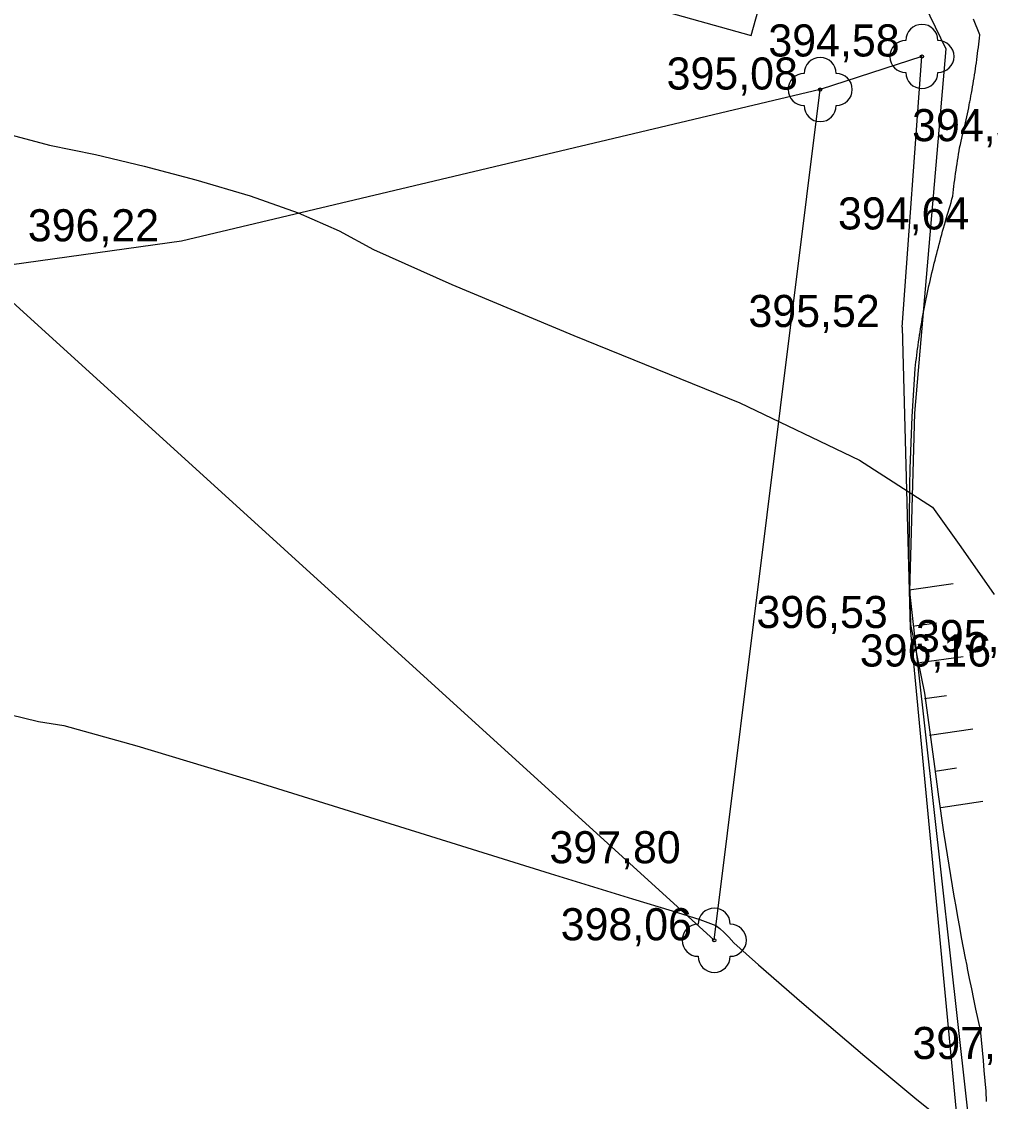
# Model space of a CAD drawing. Extents: x -574342 to -507939, y -1144044 to -1123894.
# Drawn here: x -508577.45 to -508547.27, y -1143219.6 to -1143185.95 of the extents above; entities that cross this region are included whole.
import ezdxf

# ---------------------------------------------------------------- set-up
doc = ezdxf.new("R2010")
doc.units = 0
for name, color, linetype in [('01_PARCELY_NAVRH_VHO', 7, 'Continuous'), ('01_PARCELY_NAVRH_ŽP', 7, 'Continuous'), ('1000', 7, 'Continuous'), ('54', 7, 'Continuous'), ('55', 7, 'Continuous'), ('Level 255', 7, 'Continuous'), ('VRST VEDL', 7, 'Continuous')]:
    doc.layers.add(name, color=color, linetype=linetype)

msp = doc.modelspace()

# ---------------------------------------------------------------- linework, layer by layer
for p, q in [((-508549.793, -1143203.663), (-508548.424, -1143203.467)), ((-508548.95, -1143204.696), (-508549.63, -1143204.793)), ((-508549.471, -1143205.925), (-508548.117, -1143205.737)), ((-508548.639, -1143206.964), (-508549.316, -1143207.056)), ((-508549.16, -1143208.188), (-508547.81, -1143207.995)), ((-508548.325, -1143209.216), (-508548.992, -1143209.318)), ((-508548.815, -1143210.447), (-508547.506, -1143210.242))]:
    msp.add_line(p, q)
msp.add_lwpolyline([(-508554.716, -1143186.386), (-508548.373, -1143163.737), (-508569.34, -1143157.866), (-508575.682, -1143180.515)], close=True)
at = {"layer": '01_PARCELY_NAVRH_VHO'}
msp.add_lwpolyline([(-508536.24, -1143250.83), (-508539.07, -1143243.44), (-508539.77, -1143241.25), (-508540.55, -1143238.43), (-508542.83, -1143228.38), (-508544.32, -1143217.47), (-508545.45, -1143205.07), (-508545.52, -1143198.58), (-508545.24, -1143191.32), (-508544.97, -1143188.3), (-508544.25, -1143181.83), (-508551.68, -1143170.14), (-508558.5, -1143170.32), (-508555.03, -1143173.64), (-508548.66, -1143186.8), (-508549.63, -1143198.15), (-508549.79, -1143203.71), (-508547.53, -1143223.9), (-508542.99, -1143242.68), (-508538.24, -1143253.15)], close=True, dxfattribs=at)
at = {"layer": '01_PARCELY_NAVRH_ŽP'}
msp.add_lwpolyline([(-508555.03, -1143173.64), (-508548.66, -1143186.8), (-508549.63, -1143198.15), (-508549.79, -1143203.71), (-508547.53, -1143223.9), (-508542.99, -1143242.68), (-508538.24, -1143253.15), (-508539.95, -1143255.3), (-508547.25, -1143258.62), (-508651.11, -1143191.46), (-508662.59, -1143152.85), (-508637.59, -1143153.08), (-508621.09, -1143158.13), (-508610.87, -1143164.96), (-508585.59, -1143176.01), (-508569.25, -1143175.97)], close=True, dxfattribs=at)
at = {"layer": '1000'}
msp.add_lwpolyline([(-508547.388, -1143219.601), (-508547.402, -1143219.28), (-508547.428, -1143218.961), (-508547.457, -1143218.642), (-508547.487, -1143218.324), (-508547.517, -1143218.005), (-508547.548, -1143217.687), (-508547.569, -1143217.466), (-508547.579, -1143217.367), (-508547.649, -1143217.049), (-508547.717, -1143216.731), (-508547.784, -1143216.412), (-508547.85, -1143216.093), (-508547.915, -1143215.774), (-508547.979, -1143215.454), (-508547.996, -1143215.367), (-508548.041, -1143215.134), (-508548.103, -1143214.814), (-508548.163, -1143214.494), (-508548.222, -1143214.173), (-508548.281, -1143213.852), (-508548.338, -1143213.531), (-508548.385, -1143213.258), (-508548.394, -1143213.21), (-508548.449, -1143212.888), (-508548.502, -1143212.566), (-508548.555, -1143212.244), (-508548.606, -1143211.922), (-508548.657, -1143211.599), (-508548.706, -1143211.276), (-508548.727, -1143211.138), (-508548.874, -1143210.105), (-508549.014, -1143209.009), (-508549.311, -1143206.875), (-508549.744, -1143204.738), (-508549.796, -1143202.581), (-508549.781, -1143200.423), (-508549.767, -1143199.884), (-508549.701, -1143198.268), (-508549.607, -1143196.763), (-508549.597, -1143196.659), (-508549.585, -1143196.556), (-508549.572, -1143196.452), (-508549.56, -1143196.349), (-508549.546, -1143196.245), (-508549.533, -1143196.142), (-508549.529, -1143196.117), (-508549.519, -1143196.039), (-508549.504, -1143195.935), (-508549.489, -1143195.832), (-508549.473, -1143195.729), (-508549.457, -1143195.626), (-508549.441, -1143195.522), (-508549.424, -1143195.419), (-508549.406, -1143195.316), (-508549.388, -1143195.213), (-508549.37, -1143195.11), (-508549.351, -1143195.007), (-508549.332, -1143194.905), (-508549.312, -1143194.802), (-508549.291, -1143194.699), (-508549.27, -1143194.596), (-508549.249, -1143194.494), (-508549.227, -1143194.391), (-508549.204, -1143194.289), (-508549.181, -1143194.186), (-508549.158, -1143194.084), (-508549.135, -1143193.985), (-508549.134, -1143193.982), (-508549.111, -1143193.882), (-508549.088, -1143193.782), (-508549.064, -1143193.682), (-508549.04, -1143193.583), (-508549.016, -1143193.483), (-508548.991, -1143193.383), (-508548.966, -1143193.283), (-508548.941, -1143193.183), (-508548.915, -1143193.084), (-508548.889, -1143192.984), (-508548.863, -1143192.884), (-508548.837, -1143192.785), (-508548.81, -1143192.685), (-508548.783, -1143192.586), (-508548.755, -1143192.486), (-508548.728, -1143192.386), (-508548.7, -1143192.287), (-508548.671, -1143192.187), (-508548.642, -1143192.088), (-508548.613, -1143191.988), (-508548.584, -1143191.889), (-508548.554, -1143191.79), (-508548.525, -1143191.69), (-508548.494, -1143191.591), (-508548.464, -1143191.491), (-508548.441, -1143191.392), (-508548.429, -1143191.291), (-508548.417, -1143191.19), (-508548.404, -1143191.09), (-508548.391, -1143190.989), (-508548.377, -1143190.888), (-508548.364, -1143190.788), (-508548.35, -1143190.687), (-508548.336, -1143190.587), (-508548.321, -1143190.486), (-508548.307, -1143190.386), (-508548.292, -1143190.285), (-508548.276, -1143190.185), (-508548.261, -1143190.085), (-508548.245, -1143189.984), (-508548.226, -1143189.884), (-508548.21, -1143189.813), (-508548.203, -1143189.784), (-508548.18, -1143189.684), (-508548.156, -1143189.584), (-508548.132, -1143189.485), (-508548.108, -1143189.385), (-508548.096, -1143189.335), (-508548.085, -1143189.289), (-508548.064, -1143189.197), (-508548.043, -1143189.106), (-508548.023, -1143189.014), (-508548.003, -1143188.921), (-508547.983, -1143188.829), (-508547.963, -1143188.736), (-508547.944, -1143188.644), (-508547.926, -1143188.551), (-508547.913, -1143188.486), (-508547.907, -1143188.458), (-508547.89, -1143188.365), (-508547.872, -1143188.271), (-508547.855, -1143188.178), (-508547.838, -1143188.084), (-508547.821, -1143187.99), (-508547.805, -1143187.896), (-508547.79, -1143187.802), (-508547.774, -1143187.707), (-508547.761, -1143187.622), (-508547.759, -1143187.613), (-508547.745, -1143187.518), (-508547.731, -1143187.423), (-508547.717, -1143187.328), (-508547.703, -1143187.233), (-508547.69, -1143187.138), (-508547.678, -1143187.042), (-508547.665, -1143186.946), (-508547.654, -1143186.851), (-508547.642, -1143186.755), (-508547.641, -1143186.745), (-508547.631, -1143186.659), (-508547.621, -1143186.562), (-508547.61, -1143186.466), (-508547.601, -1143186.369), (-508547.793, -1143185.882)], dxfattribs=at)
at = {"layer": '54'}
for centre in [(-508549.4, -1143187.04), (-508552.57, -1143188.07), (-508555.87, -1143214.58)]:
    msp.add_circle(centre, 0.05, dxfattribs=at)
for centre, start, end in [((-508549.4, -1143186.54), 0, 180), ((-508549.9, -1143187.04), 90, 270), ((-508548.9, -1143187.04), 270, 90), ((-508552.57, -1143187.57), 0, 180), ((-508553.07, -1143188.07), 90, 270), ((-508552.07, -1143188.07), 270, 90), ((-508549.4, -1143187.54), 180, 0), ((-508552.57, -1143188.57), 180, 0), ((-508555.87, -1143214.08), 0, 180), ((-508556.37, -1143214.58), 90, 270), ((-508555.37, -1143214.58), 270, 90), ((-508555.87, -1143215.08), 180, 0)]:
    msp.add_arc(centre, 0.5, start, end, dxfattribs=at)
at = {"layer": '55'}
for p, q in [((-508552.57, -1143188.07), (-508572.47, -1143192.8)), ((-508552.57, -1143188.07), (-508572.47, -1143192.8)), ((-508555.87, -1143214.58), (-508552.57, -1143188.07)), ((-508555.87, -1143214.58), (-508552.57, -1143188.07)), ((-508572.47, -1143192.8), (-508578.85, -1143193.68)), ((-508572.47, -1143192.8), (-508578.85, -1143193.68)), ((-508555.87, -1143214.58), (-508578.85, -1143193.68)), ((-508555.87, -1143214.58), (-508578.85, -1143193.68))]:
    msp.add_line(p, q, dxfattribs=at)
for points in [[(-508550.02, -1143195.47), (-508549.4, -1143187.04), (-508552.57, -1143188.07)], [(-508550.02, -1143195.47), (-508549.4, -1143187.04), (-508552.57, -1143188.07)], [(-508550.02, -1143195.47), (-508549.77, -1143204.85), (-508547.83, -1143225.16)], [(-508550.02, -1143195.47), (-508549.77, -1143204.85), (-508547.83, -1143225.16)]]:
    msp.add_lwpolyline(points, dxfattribs=at)
at = {"layer": 'VRST VEDL'}
for points in [[(-508578.414, -1143189.312), (-508576.584, -1143189.808), (-508575.149, -1143190.097), (-508573.628, -1143190.456), (-508572.02, -1143190.886), (-508570.325, -1143191.387), (-508568.837, -1143191.915), (-508567.558, -1143192.471), (-508566.486, -1143193.055), (-508564.048, -1143194.143), (-508560.243, -1143195.735), (-508555.072, -1143197.832), (-508551.349, -1143199.615), (-508549.073, -1143201.087), (-508548.245, -1143202.246), (-508547.605, -1143203.153), (-508547.152, -1143203.809)], [(-508577.821, -1143207.549), (-508576.92, -1143207.76), (-508576.13, -1143207.891), (-508573.861, -1143208.523), (-508570.111, -1143209.655), (-508564.88, -1143211.288), (-508560.982, -1143212.499), (-508558.417, -1143213.289), (-508557.184, -1143213.658), (-508556.32, -1143213.935), (-508555.826, -1143214.121), (-508555.701, -1143214.216), (-508555.564, -1143214.338), (-508555.416, -1143214.487), (-508555.256, -1143214.664), (-508554.496, -1143215.341), (-508553.137, -1143216.518), (-508551.177, -1143218.195), (-508549.563, -1143219.538), (-508548.295, -1143220.549)]]:
    msp.add_lwpolyline(points, dxfattribs=at)

# ---------------------------------------------------------------- texts
at = {"layer": 'Level 255'}
for s, p in [('394,58', (-508554.185, -1143187.04)), ('395,08', (-508557.355, -1143188.07)), ('394,39', (-508549.705, -1143189.68)), ('394,64', (-508552.015, -1143192.43)), ('396,22', (-508577.255, -1143192.8)), ('395,52', (-508554.805, -1143195.47)), ('396,53', (-508554.555, -1143204.85)), ('395,93', (-508549.585, -1143205.6)), ('396,16', (-508551.335, -1143206.05)), ('397,80', (-508561.005, -1143212.18)), ('398,06', (-508560.655, -1143214.58)), ('397,21', (-508549.695, -1143218.28))]:
    msp.add_text(s, height=1, dxfattribs=at).set_placement(p)

doc.saveas('drawing.dxf')
